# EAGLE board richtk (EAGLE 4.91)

Size 36.9 x 35.21 mm. Coordinates in mm from the lower left corner, seen from the top.
Outline: 0,0 36.9,0 36.9,35.21 0,35.21 0,0
Copper layers (1*16): Top 0.035mm / dielectric 1.5mm / Bottom 0.035mm
Design rules "default": minimum track width 10mil, minimum drill 24mil, track to track 8mil, track to pad 8mil, pad to pad 8mil, via to via 8mil, smd to smd 8mil, copper to edge 40mil, drill to drill 8mil, minimum pad ring 10mil, minimum via ring 8mil, stop-mask expansion 4mil, vias tented up to drill 0mil, thermal gap 10mil

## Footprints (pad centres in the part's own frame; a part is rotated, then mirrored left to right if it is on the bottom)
C0805 = smd 1.3 x 1.5: 1 -0.95,0; 2 0.95,0
R0805 = smd 1.3 x 1.5: 1 -0.95,0; 2 0.95,0

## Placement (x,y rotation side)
C1  [C0805]  18.4,26.31 180 top
C2  [C0805]  20.63,13.29 90 top
C3  [C0805]  27.72,16.3 0 top
R1  [R0805]  15.43,24.31 90 top
R2  [R0805]  18.38,10.08 0 top
R3  [R0805]  22.78,10.15 0 top
R4  [R0805]  23.09,16.27 0 top
R5  [R0805]  23.06,26.28 0 top

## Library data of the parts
C1-C3 R1-R5 = rcl

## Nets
N$1: R1.2 R5.2
N$2: C1.1 R1.1 R2.2
N$3: C1.2 R3.2
N$4: C2.1 R4.2
N$5: C3.1 R2.1 R3.1
N$6: C3.2 R4.1
N$7: C2.2 R5.1

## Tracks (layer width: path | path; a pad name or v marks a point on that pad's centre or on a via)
N$1  (1 unrouted)
N$2  (2 unrouted)
N$3  (1 unrouted)
N$4  (1 unrouted)
N$5  (2 unrouted)
N$6  (1 unrouted)
N$7  (1 unrouted)
(copper drawn outside any net)
  shapes: Top area x32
